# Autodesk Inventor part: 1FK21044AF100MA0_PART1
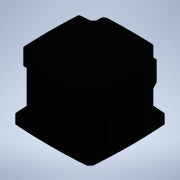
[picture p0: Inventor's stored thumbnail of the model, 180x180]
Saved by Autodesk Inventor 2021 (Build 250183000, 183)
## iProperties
Created: 2025-04
Part Number: 1FK21044AF100MA0_PART1
Material: Generic
Catalog Web Link: www.3dfindit.com
Description: -Servo synchronous motor
Document SubType Name: Modeling
Designer: psAdmin
Mass: 314.393 g
Surface Area: 353.669 cm^2
Volume: 314.393 cm^3
Density: 1 g/cm^3
Appearance: PSOLRGB-176-176-176
Category: PARTsolutions
Title: 1FK21044AF100MA0_PART1
Author: Cadenas PARTsolutions
Comments: Servo synchronous motor
Sending System: PARTsolutions
Preprocessor: ST-DEVELOPER v19.3
PSOL_IDENT_0: {$CADENAS_DATA/23d-libs/siemens_ag/_cat_/ec/e4/1fk21044af100ma0.prj},213 {VTYP=3D},{NB=1FK21044AF100
PSOL_IDENT_1: MA0_PART1},{LINA=1FK21044AF100MA0_PART1},{NN=1FK21044AF100MA0_PART1},{NOPRJ=TRUE},{DATE=19.08.2025 1
PSOL_IDENT_2: 4:01:05},{GEOMDATE=30.07.2025 02:01:01},{VERSION=},{LINEID=10},{WBVAR=},{WBNUMERIC=}  {NB=1FK21044AF
PSOL_IDENT_3: 100MA0_PART1},{LINA=1FK21044AF100MA0_PART1},{KT=DUMMY},{PREVIEW=../../../_pool_/cb/72/p_d211_xx_0043
PSOL_IDENT_4: 4j.png},{DESCSHORT=SIMOTICS S-1FK2 HD, SINAMICS S210 3AC 400V-480V, 1.27 Nm, 3000 rpm},{DESCLONG=SIM
PSOL_IDENT_5: OTICS S-1FK2 HD servo motor M0=1.27 Nm; PN = 0.4 kW at nN=3000 rpm (380-480 V); PN = 0.2 kW at nN=15
PSOL_IDENT_6: 00 rpm (200-240 V); with holding brake; degree of protection IP64; cylindrical shaft D19x40mm; absol
PSOL_IDENT_7: ute encoder 22-bit + 12-bit multiturn (encoder AM22DQC); with OCC interface; plug size M17, rotatabl
PSOL_IDENT_8: e; SIMOTICS S-1FK2 servomotorfor a wide range of uses in industrial environments. SIMOTICS S‑1FK2 se
PSOL_IDENT_9: rvomotors are compact synchronous motors with a high dynamic performance that set themselves apart a
PSOL_IDENT_10: s a result of their high power density, degree of protection and overload capability. The motors are
PSOL_IDENT_11: available in two variants: as High Dynamic variant (highest dynamic performance as a result of the
PSOL_IDENT_12: low intrinsic moment of inertia for applications demanding a high dynamic performance with low moved
PSOL_IDENT_13: masses) - and as Compact variant (precise and stable closed-loop control for medium up to large mov
PSOL_IDENT_14: ed masses as a result of a medium intrinsic moment of inertia). SIMOTICSS‑1FK2 servomotors fully exp
PSOL_IDENT_15: loit their strengths in a system with the SINAMICSS210 frequency converter and simple connection usi
PSOL_IDENT_16: ng the one cable connection (OCC). Advantages include the short control and positioning times, fast
PSOL_IDENT_17: and precise correction of disturbing quantities as well as stable control with a high dynamic perfor
PSOL_IDENT_18: mance. The servo motors can be configured to address a wide range of requirements. For example with
PSOL_IDENT_19: and without holding brake, IP64 or IP65 degree of protection, singleturn or multiturn absolute encod
PSOL_IDENT_20: ers - to name just a few. Further, the servomotors are available in different shaft heights extendin
PSOL_IDENT_21: g from 20 to 100. A shaft sealing ring is available to achieve an IP65 degree of protection and for
PSOL_IDENT_22: subsequent mounting at the motor or as spare part. SIMOTICS - the optimum motor for each and every m
PSOL_IDENT_23: otion control application.},{INTNO=195125043275},{SUPPLIERALTNO=1FK2104-4AF10-0MA0},{MANUID=1FK21044
PSOL_IDENT_24: AF100MA0},{MANUNAME=Siemens},{MANUTYPEDESC=Synchronous motor 1FK2-HD 1.27 NM},{AAU732=SIMOTICS},{AAO
PSOL_IDENT_25: 057=S-1FK2},{AAU734=SIMOTICS S-1FK2 HD servo motor M0=1.27 Nm; PN = 0.4 kW at nN=3000 rpm (380-480 V
PSOL_IDENT_26: ); PN = 0.2 kW at nN=1500 rpm (200-240 V); with holding brake; degree of protection IP64; cylindrica
PSOL_IDENT_27: l shaft D19x40mm; absolute encoder 22-bit + 12-bit multiturn (encoder AM22DQC); with OCC interface;
PSOL_IDENT_28: plug size M17, rotatable;},{AAW338=Synchronous motor 1FK2-HD 1.27 NM},{AAO742=SIMOTICS},{AAO663=4042
PSOL_IDENT_29: 948694015},{NOCUPEROU=1},{PRICEQUANTITY=1},{QUANTITYMIN=1},{QUANTITYINT=1},{CTN=85015100},{COO=DE},{
PSOL_IDENT_30: AAO676=1FK2104-4AF10-0MA0},{AAO677=Siemens AG},{ORDERUNIT=C62},{CONTENTUNIT=C62}
NB: 1FK21044AF100MA0_PART1
NT: Servo synchronous motor
NBSYN: $MANUID._PART1
LINA: 1FK21044AF100MA0_PART1
CATALOG: SIEMENS
PREVIEW: ../../../_pool_/cb/72/p_d211_xx_00434j.png
DESCSHORT: SIMOTICS S-1FK2 HD, SINAMICS S210 3AC 400V-480V, 1.27 Nm, 3000 rpm
DESCLONG: SIMOTICS S-1FK2 HD servo motor M0=1.27 Nm; PN = 0.4 kW at nN=3000 rpm (380-480 V); PN = 0.2 kW at nN=1500 rpm (200-240 V); with holding brake; degree of protect
INTNO: 195125043275
SUPPLIERALTNO: 1FK2104-4AF10-0MA0
MANUID: 1FK21044AF100MA0
MANUNAME: Siemens
MANUTYPEDESC: Synchronous motor 1FK2-HD 1.27 NM
AAU732: SIMOTICS
AAO057: S-1FK2
AAU734: SIMOTICS S-1FK2 HD servo motor M0=1.27 Nm; PN = 0.4 kW at nN=3000 rpm (380-480 V); PN = 0.2 kW at nN=1500 rpm (200-240 V); with holding brake; degree of protect
AAW338: Synchronous motor 1FK2-HD 1.27 NM
AAO742: SIMOTICS
AAO663: 4042948694015.0
NOCUPEROU: 1
PRICEQUANTITY: 1
QUANTITYMIN: 1
QUANTITYINT: 1
CTN: 85015100
COO: DE
ARTICLENO: 1FK21044AF100MA0_PART1
BOMINFO: 1FK21044AF100MA0_PART1
CREATOR: CADENAS GmbH
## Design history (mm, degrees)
feature "2025_04_17_15_33_01_0517"
node "ECLASS_CAX_IMPORTER_001_CP_0_XY"
node "ECLASS_CAX_IMPORTER_001_CP_0_YZ"
node "ECLASS_CAX_IMPORTER_001_CP_0_ZX"
node "ECLASS_CAX_IMPORTER_001_CP_0_X"
node "ECLASS_CAX_IMPORTER_001_CP_0_Y"
node "ECLASS_CAX_IMPORTER_001_CP_0_Z"
node "ECLASS_CAX_IMPORTER_001_CP_0_Center"
node "ECLASS_CAX_IMPORTER_001_CP_1_XY"
node "ECLASS_CAX_IMPORTER_001_CP_1_YZ"
node "ECLASS_CAX_IMPORTER_001_CP_1_ZX"
node "ECLASS_CAX_IMPORTER_001_CP_1_X"
node "ECLASS_CAX_IMPORTER_001_CP_1_Y"
node "ECLASS_CAX_IMPORTER_001_CP_1_Z"
node "ECLASS_CAX_IMPORTER_001_CP_1_Center"
body "Solid1"
